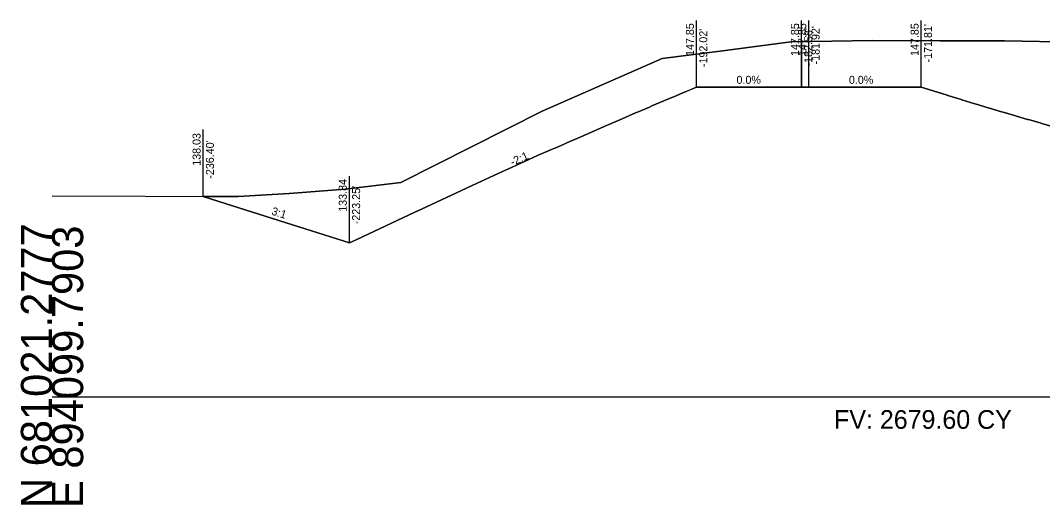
# Model space of a CAD drawing. Extents: x -26 to 4403, y -13 to 9578.
# Drawn here: x 1997.2 to 2089.1, y -9.7 to 33.8 of the extents above; entities that cross this region are included whole.
import ezdxf

# ---------------------------------------------------------------- set-up
doc = ezdxf.new("R2010")
doc.units = 0
for name, color, linetype in [('Draft_XS_Grid', 7, 'Continuous'), ('DRAINAGE_SPUR_DIKES', 7, 'Continuous'), ('DTM_CORRIDOR', 7, 'Continuous'), ('DTM_TEMP_DROP', 7, 'Continuous'), ('DTM_X_GROUND', 7, 'Continuous'), ('XS_CELL', 7, 'Continuous'), ('XS_M_SHAPES_EARTHWORK', 7, 'Continuous'), ('XS_P_GROUND', 7, 'Continuous'), ('XS_P_TX_CLEARZONE', 7, 'Continuous'), ('XS_P_TX_FS_BS', 7, 'Continuous'), ('XS_SHEET_EW_TX_VOLUME', 7, 'Continuous')]:
    doc.layers.add(name, color=color, linetype=linetype)

msp = doc.modelspace()

# ---------------------------------------------------------------- linework, layer by layer
at = {"layer": 'DRAINAGE_SPUR_DIKES'}
msp.add_lwpolyline([(2057.978, 27.85), (2078.191, 27.85)], dxfattribs=at)
at = {"layer": 'DTM_X_GROUND'}
msp.add_lwpolyline([(2000, 18.081), (2016.738, 18.017), (2021.336, 18.271), (2026.377, 18.668), (2031.376, 19.287), (2044.087, 25.683), (2054.877, 30.415), (2060.086, 31.086), (2066.447, 31.939), (2073.829, 32.038), (2079.891, 32.016), (2085.664, 32.011), (2091.991, 31.895), (2096.952, 31.53), (2101.603, 31.182), (2122.191, 22.251), (2133.153, 16.884), (2137.339, 15.992), (2166.759, 11.226), (2179.976, 11.364), (2202.58, 11.905)], dxfattribs=at)
at = {"layer": 'XS_CELL'}
msp.add_line((2000, 0), (2250, 0), dxfattribs=at)
at = {"layer": 'XS_M_SHAPES_EARTHWORK'}
msp.add_lwpolyline([(2013.602, 18.029), (2016.738, 18.017), (2021.336, 18.271), (2026.377, 18.668), (2031.376, 19.287), (2044.087, 25.683), (2054.877, 30.415), (2060.086, 31.086), (2066.447, 31.939), (2067.423, 31.952), (2067.423, 27.85), (2067.179, 27.85), (2067.142, 27.85), (2066.026, 27.85), (2065.802, 27.85), (2064.822, 27.85), (2064.389, 27.85), (2064.113, 27.85), (2063.942, 27.85), (2063.355, 27.85), (2062.866, 27.85), (2062.191, 27.85), (2061.258, 27.85), (2060.794, 27.85), (2059.572, 27.85), (2059.34, 27.85), (2057.978, 27.85), (2057.799, 27.776), (2057.792, 27.773), (2056.841, 27.375), (2056.795, 27.356), (2055.932, 26.993), (2055.747, 26.914), (2053.96, 26.156), (2053.733, 26.059), (2052.674, 25.606), (2052.492, 25.528), (2051.872, 25.261), (2051.275, 25.002), (2049.655, 24.301), (2048.806, 23.929), (2047.294, 23.268), (2046.588, 22.957), (2045.519, 22.485), (2045.226, 22.36), (2045.33, 22.405), (2044.932, 22.236), (2043.679, 21.688), (2041.337, 20.625), (2040.521, 20.253), (2037.802, 19.003), (2036.83, 18.555), (2033.246, 16.888), (2032.632, 16.603), (2027.926, 14.392), (2027.806, 14.336), (2026.752, 13.836), (2022.193, 15.28), (2017.358, 16.824), (2015.572, 17.395)], close=True, dxfattribs=at)
msp.add_lwpolyline([(2089.964, 24.324), (2089.047, 24.581), (2088.871, 24.63), (2088.337, 24.782), (2088.246, 24.808), (2087.829, 24.928), (2087.745, 24.951), (2086.753, 25.239), (2086.583, 25.288), (2085.553, 25.591), (2085.407, 25.633), (2084.337, 25.952), (2084.216, 25.988), (2083.412, 26.23), (2083.338, 26.253), (2083.033, 26.345), (2083.005, 26.354), (2081.849, 26.707), (2081.77, 26.731), (2080.57, 27.103), (2080.518, 27.119), (2079.272, 27.508), (2079.248, 27.516), (2078.191, 27.85), (2078.052, 27.85), (2077.96, 27.85), (2076.638, 27.85), (2075.271, 27.85), (2074.999, 27.85), (2073.827, 27.85), (2072.322, 27.85), (2071.644, 27.85), (2070.744, 27.85), (2069.046, 27.85), (2067.818, 27.85), (2067.422, 27.85), (2067.422, 31.952), (2073.829, 32.038), (2079.891, 32.016), (2085.664, 32.011), (2091.991, 31.895)], dxfattribs=at)
at = {"layer": 'XS_P_GROUND'}
for p, q in [((2057.978, 27.85), (2059.34, 27.85)), ((2059.34, 27.85), (2059.572, 27.85)), ((2061.258, 27.85), (2062.191, 27.85)), ((2065.802, 27.85), (2066.026, 27.85)), ((2066.026, 27.85), (2067.142, 27.85)), ((2078.052, 27.85), (2078.191, 27.85))]:
    msp.add_line(p, q, dxfattribs=at)
for points in [[(2133.153, 16.884), (2122.191, 22.251), (2101.603, 31.182), (2096.952, 31.53), (2091.991, 31.895), (2085.664, 32.011), (2079.891, 32.016), (2073.829, 32.038), (2066.447, 31.939), (2060.086, 31.086), (2054.877, 30.415), (2044.087, 25.683), (2031.376, 19.287), (2026.377, 18.668), (2021.336, 18.271), (2016.738, 18.017), (2013.602, 18.029)], [(2057.978, 27.85), (2057.799, 27.776), (2057.792, 27.773), (2056.841, 27.375), (2056.795, 27.356), (2055.932, 26.993), (2055.747, 26.914), (2053.96, 26.156), (2053.733, 26.059), (2052.674, 25.606), (2052.492, 25.528), (2051.872, 25.261), (2051.275, 25.002), (2049.655, 24.301), (2048.806, 23.929), (2047.294, 23.268), (2046.588, 22.957), (2045.519, 22.485), (2045.226, 22.36), (2045.33, 22.405), (2044.932, 22.236), (2043.679, 21.688), (2041.337, 20.625), (2040.521, 20.253), (2037.802, 19.003), (2036.83, 18.555), (2033.246, 16.888), (2032.632, 16.603), (2027.926, 14.392), (2027.806, 14.336), (2026.752, 13.836)], [(2045.331, 22.405), (2045.519, 22.485), (2046.588, 22.957), (2047.294, 23.268), (2048.806, 23.929), (2049.655, 24.301), (2051.275, 25.002), (2051.872, 25.261), (2052.492, 25.528), (2052.674, 25.606), (2053.733, 26.059), (2053.96, 26.156), (2055.747, 26.914), (2055.932, 26.993), (2056.795, 27.356), (2056.841, 27.375), (2057.799, 27.776), (2057.978, 27.85)], [(2067.423, 27.85), (2067.179, 27.85), (2067.142, 27.85), (2066.026, 27.85), (2065.802, 27.85), (2064.822, 27.85), (2064.389, 27.85), (2064.113, 27.85), (2063.942, 27.85), (2063.355, 27.85), (2062.866, 27.85), (2062.191, 27.85), (2061.258, 27.85), (2060.794, 27.85), (2059.572, 27.85), (2059.34, 27.85), (2057.978, 27.85)], [(2059.572, 27.85), (2060.794, 27.85), (2061.258, 27.85)], [(2062.191, 27.85), (2062.866, 27.85), (2063.355, 27.85)], [(2063.355, 27.85), (2063.942, 27.85), (2064.113, 27.85), (2064.389, 27.85)], [(2064.389, 27.85), (2064.822, 27.85), (2065.802, 27.85)], [(2067.142, 27.85), (2067.179, 27.85), (2067.423, 27.85)], [(2067.422, 27.85), (2067.818, 27.85), (2069.046, 27.85), (2070.744, 27.85), (2071.644, 27.85), (2072.322, 27.85), (2073.827, 27.85), (2074.999, 27.85), (2075.271, 27.85), (2076.638, 27.85), (2077.96, 27.85), (2078.052, 27.85), (2078.191, 27.85)], [(2067.423, 27.85), (2067.818, 27.85), (2069.046, 27.85)], [(2069.046, 27.85), (2070.744, 27.85), (2071.644, 27.85), (2072.322, 27.85), (2073.827, 27.85), (2074.999, 27.85)], [(2074.999, 27.85), (2075.271, 27.85), (2076.638, 27.85)], [(2076.638, 27.85), (2077.96, 27.85), (2078.052, 27.85)], [(2078.191, 27.85), (2079.248, 27.516), (2079.272, 27.508), (2080.518, 27.119), (2080.57, 27.103), (2081.77, 26.731), (2081.849, 26.707), (2083.005, 26.354), (2083.033, 26.345), (2083.338, 26.253), (2083.412, 26.23), (2084.216, 25.988), (2084.337, 25.952), (2085.407, 25.633), (2085.553, 25.591), (2086.583, 25.288), (2086.753, 25.239), (2087.745, 24.951), (2087.829, 24.928), (2088.246, 24.808), (2088.337, 24.782), (2088.871, 24.63), (2089.047, 24.581), (2089.964, 24.324)], [(2078.191, 27.85), (2079.248, 27.516), (2079.272, 27.508), (2080.518, 27.119), (2080.57, 27.103), (2081.77, 26.731), (2081.849, 26.707), (2083.005, 26.354), (2083.033, 26.345), (2083.338, 26.253), (2083.412, 26.23), (2084.216, 25.988), (2084.337, 25.952), (2085.407, 25.633), (2085.553, 25.591), (2086.583, 25.288), (2086.753, 25.239), (2087.745, 24.951), (2087.829, 24.928), (2088.246, 24.808), (2088.337, 24.782), (2088.871, 24.63), (2089.047, 24.581), (2089.964, 24.324)], [(2026.752, 13.836), (2027.806, 14.336), (2027.926, 14.392), (2032.632, 16.603), (2033.246, 16.888), (2036.83, 18.555), (2037.802, 19.003), (2040.521, 20.253), (2041.337, 20.625), (2043.679, 21.688), (2044.932, 22.236), (2045.225, 22.36), (2045.33, 22.405)], [(2045.33, 22.405), (2045.331, 22.405)], [(2026.752, 13.836), (2022.193, 15.28), (2017.358, 16.824), (2015.572, 17.395), (2013.602, 18.029)], [(2013.602, 18.029), (2015.572, 17.395), (2017.358, 16.824), (2022.193, 15.28), (2026.752, 13.836)]]:
    msp.add_lwpolyline(points, dxfattribs=at)
at = {"layer": 'XS_P_TX_CLEARZONE'}
for p, q in [((2057.978, 27.85), (2057.978, 33.85)), ((2057.978, 27.85), (2057.978, 33.85)), ((2057.978, 27.85), (2057.978, 33.85)), ((2057.978, 27.85), (2057.978, 33.85)), ((2057.978, 27.85), (2057.978, 33.85)), ((2057.978, 27.85), (2057.978, 33.85)), ((2067.422, 27.85), (2067.422, 33.85)), ((2067.422, 27.85), (2067.422, 33.85)), ((2067.422, 27.85), (2067.422, 33.85)), ((2067.423, 27.85), (2067.423, 33.85)), ((2067.423, 27.85), (2067.423, 33.85)), ((2067.423, 27.85), (2067.423, 33.85)), ((2067.423, 27.85), (2067.423, 33.85)), ((2067.423, 27.85), (2067.423, 33.85)), ((2067.423, 27.85), (2067.423, 33.85)), ((2068.084, 27.85), (2068.084, 33.85)), ((2068.084, 27.85), (2068.084, 33.85)), ((2068.084, 27.85), (2068.084, 33.85)), ((2078.191, 27.85), (2078.191, 33.85)), ((2078.191, 27.85), (2078.191, 33.85)), ((2078.191, 27.85), (2078.191, 33.85)), ((2078.191, 27.85), (2078.191, 33.85)), ((2078.191, 27.85), (2078.191, 33.85)), ((2078.191, 27.85), (2078.191, 33.85)), ((2013.602, 18.029), (2013.602, 24.029)), ((2013.602, 18.029), (2013.602, 24.029)), ((2013.602, 18.029), (2013.602, 24.029)), ((2026.752, 13.836), (2026.752, 19.836)), ((2026.752, 13.836), (2026.752, 19.836)), ((2026.752, 13.836), (2026.752, 19.836))]:
    msp.add_line(p, q, dxfattribs=at)

# ---------------------------------------------------------------- texts
at = {"layer": 'Draft_XS_Grid'}
msp.add_text('-', height=0.0001, dxfattribs=at).set_placement((2000, 0))
at = {"layer": 'DRAINAGE_SPUR_DIKES'}
msp.add_text('X', height=0.12, dxfattribs=at).set_placement((2013.563, 17.969))
at = {"layer": 'DTM_CORRIDOR'}
msp.add_text('X', height=0.12, dxfattribs=at).set_placement((2026.712, 13.776))
at = {"layer": 'DTM_TEMP_DROP'}
for p in [(2057.938, 27.79), (2067.383, 27.79), (2067.384, 27.79), (2078.152, 27.79)]:
    msp.add_text('X', height=0.12, dxfattribs=at).set_placement(p)
at = {"layer": 'XS_CELL'}
for s, p in [('N 681021.2777', (2000, -10)), ('E 894099.7903', (2002.8, -10))]:
    msp.add_text(s, height=2.8, rotation=90, dxfattribs=at).set_placement(p)
at = {"layer": 'XS_P_TX_CLEARZONE'}
for s, p in [('147.85', (2057.738, 30.654)), ('147.85', (2057.738, 30.654)), ('147.85', (2057.738, 30.654)), ('147.85', (2057.738, 30.654)), ('147.85', (2057.738, 30.654)), ('147.85', (2057.738, 30.654)), ('147.85', (2067.182, 30.654)), ('147.85', (2067.182, 30.654)), ('147.85', (2067.182, 30.654)), ('147.85', (2067.183, 30.654)), ('147.85', (2067.183, 30.654)), ('147.85', (2067.183, 30.654)), ('147.85', (2067.183, 30.654)), ('147.85', (2067.183, 30.654)), ('147.85', (2067.183, 30.654)), ('147.85', (2067.844, 30.654)), ('147.85', (2067.844, 30.654)), ('147.85', (2067.844, 30.654)), ("-182.58'", (2068.382, 29.713)), ("-182.58'", (2068.382, 29.713)), ("-182.58'", (2068.382, 29.713)), ("-182.58'", (2068.383, 29.713)), ("-182.58'", (2068.383, 29.713)), ("-182.58'", (2068.383, 29.713)), ("-182.58'", (2068.383, 29.713)), ("-182.58'", (2068.383, 29.713)), ("-182.58'", (2068.383, 29.713)), ("-181.92'", (2069.044, 29.895)), ("-181.92'", (2069.044, 29.895)), ("-181.92'", (2069.044, 29.895)), ('147.85', (2077.951, 30.654)), ('147.85', (2077.951, 30.654)), ('147.85', (2077.951, 30.654)), ('147.85', (2077.951, 30.654)), ('147.85', (2077.951, 30.654)), ('147.85', (2077.951, 30.654)), ("-171.81'", (2079.151, 30.076)), ("-171.81'", (2079.151, 30.076)), ("-171.81'", (2079.151, 30.076)), ("-171.81'", (2079.151, 30.076)), ("-171.81'", (2079.151, 30.076)), ("-171.81'", (2079.151, 30.076)), ("-192.02'", (2058.938, 29.656)), ("-192.02'", (2058.938, 29.656)), ("-192.02'", (2058.938, 29.656)), ("-192.02'", (2058.938, 29.656)), ("-192.02'", (2058.938, 29.656)), ("-192.02'", (2058.938, 29.656)), ('138.03', (2013.362, 20.776)), ('138.03', (2013.362, 20.776)), ('138.03', (2013.362, 20.776)), ("-236.40'", (2014.562, 19.62)), ("-236.40'", (2014.562, 19.62)), ("-236.40'", (2014.562, 19.62)), ('133.84', (2026.512, 16.64)), ('133.84', (2026.512, 16.64)), ('133.84', (2026.512, 16.64)), ("-223.25'", (2027.712, 15.518)), ("-223.25'", (2027.712, 15.518)), ("-223.25'", (2027.712, 15.518))]:
    msp.add_text(s, height=0.72, rotation=90, dxfattribs=at).set_placement(p)
at = {"layer": 'XS_P_TX_FS_BS'}
for p in [(2061.57, 28.15), (2061.57, 28.15), (2061.57, 28.15), (2071.677, 28.15), (2071.677, 28.15), (2071.677, 28.15)]:
    msp.add_text('0.0%', height=0.72, dxfattribs=at).set_placement(p)
for s, rotation, p in [('-2:1', 24.17042, (2041.414, 20.745)), ('-2:1', 24.17042, (2041.414, 20.745)), ('-2:1', 24.17042, (2041.414, 20.745)), ('3:1', 342.31437, (2019.684, 16.404)), ('3:1', 342.31437, (2019.684, 16.404)), ('3:1', 342.31437, (2019.684, 16.404))]:
    msp.add_text(s, height=0.72, rotation=rotation, dxfattribs=at).set_placement(p)
at = {"layer": 'XS_SHEET_EW_TX_VOLUME'}
msp.add_text('FV: 2679.60 CY', height=1.68, dxfattribs=at).set_placement((2070.346, -2.88))

doc.saveas('drawing.dxf')
